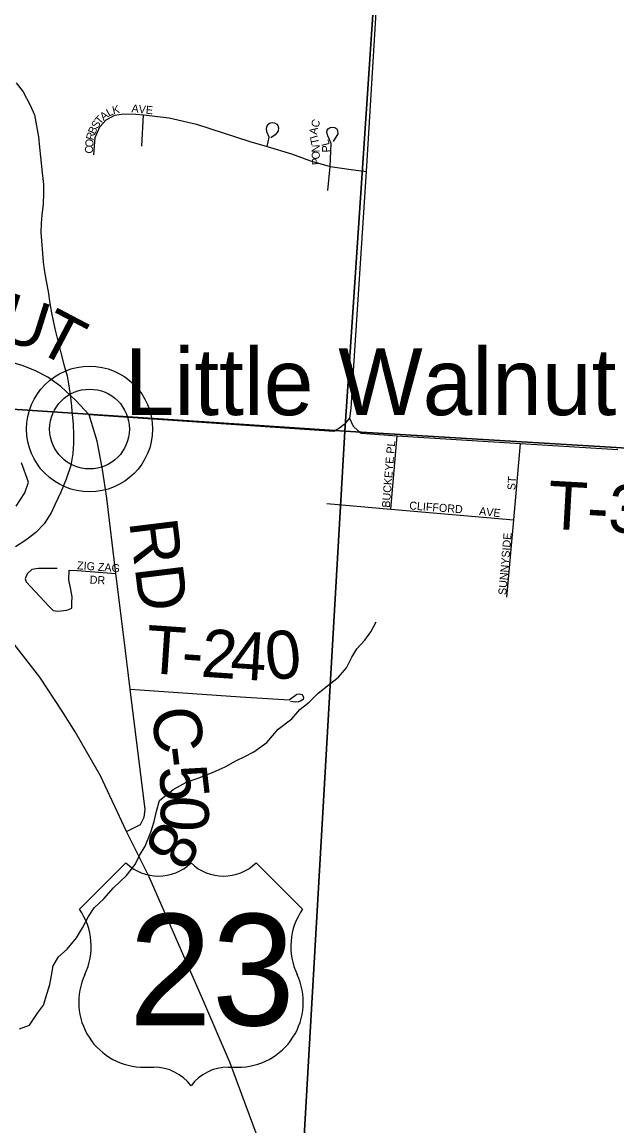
# Model space of a CAD drawing. Extents: x 1643459 to 2064572, y 425441 to 780708.
# Drawn here: x 1835489 to 1839200, y 609399 to 616295 of the extents above; entities that cross this region are included whole.
import ezdxf

# ---------------------------------------------------------------- set-up
doc = ezdxf.new("R2010")
doc.units = 0
for name, color, linetype in [('GE_P_Alignment_100_Curve_Data', 7, 'Continuous'), ('GM_X_Airport_Text_Class_2', 7, 'Continuous'), ('GM_X_County', 7, 'Continuous'), ('GM_X_Major_River', 7, 'Continuous'), ('GM_X_Major_River_Text', 7, 'Continuous'), ('GM_X_Minor_Lake', 7, 'Continuous'), ('GM_X_Rail_Line', 7, 'Continuous'), ('GM_X_Section_Text', 7, 'Continuous'), ('GM_X_State_Route', 7, 'Continuous'), ('GM_X_Township', 7, 'Continuous'), ('GM_X_Township_ROW', 7, 'Continuous'), ('GM_X_Unincorporated_Text', 7, 'Continuous'), ('GM_X_US_Route', 7, 'Continuous'), ('RD_X_Wall', 7, 'Continuous'), ('SH_Named_Boundary', 7, 'Continuous')]:
    doc.layers.add(name, color=color, linetype=linetype)

msp = doc.modelspace()

# ---------------------------------------------------------------- linework, layer by layer
at = {"layer": 'GE_P_Alignment_100_Curve_Data'}
for radius in [392.8, 249]:
    msp.add_circle((1835910, 613753), radius, dxfattribs=at)
at = {"layer": 'GM_X_County'}
for points in [[(1835935.9, 615466.4), (1835945.4, 615575.1), (1835973.8, 615641.3), (1836013.9, 615683.8), (1836068.3, 615714.5), (1836122.6, 615721.6), (1836198.2, 615719.3), (1836246.6, 615716.6), (1836406.2, 615698), (1836576.3, 615657.8), (1836909.5, 615549.1), (1837018.2, 615518.4), (1837169.5, 615471.1), (1837287.6, 615428.5), (1837410.5, 615393.1), (1837528.6, 615375.7), (1837635, 615362.4)], [(1836235.4, 615520.4), (1836246.6, 615716.6)], [(1837018.2, 615518.4), (1837031.1, 615575.8), (1837016.9, 615608.6), (1837013.3, 615632.1), (1837018.3, 615647), (1837027.6, 615659.9), (1837037.5, 615665.5), (1837051.1, 615668.4), (1837064.6, 615666.3), (1837078.1, 615657.7), (1837084.5, 615648.5), (1837089.5, 615633.5), (1837087.4, 615614.3), (1837067.4, 615590.8), (1837041.8, 615572.2)], [(1837410.5, 615393.1), (1837417.8, 615537.1), (1837408.1, 615561.7), (1837396.7, 615585.1), (1837390.4, 615605.1), (1837393.2, 615619.3), (1837399.5, 615627.9), (1837410.9, 615636.5), (1837423.5, 615638.2), (1837440.1, 615636.5), (1837452, 615629.1), (1837457.7, 615618.2), (1837458.9, 615596.5), (1837429.2, 615548.4)], [(1837397.8, 615242.1), (1837410.5, 615393.1)], [(1837789.4, 613252.3), (1837829.5, 613710.6)], [(1838514.2, 612702.1), (1838556.5, 613185.3), (1838598.3, 613663.2)], [(1837390.9, 613287.2), (1837789.4, 613252.3), (1838556.5, 613185.3)], [(1835707.2, 612880.9), (1835591.4, 612882), (1835550.1, 612876.3), (1835521.4, 612848.8), (1835508.8, 612816.7), (1835514.5, 612798.3), (1835655.6, 612645.9), (1835683.1, 612619.5), (1835712.9, 612616), (1835769.1, 612621.8), (1835798.9, 612634.4), (1835798.9, 612669.9), (1835802.3, 612705.5), (1835793.1, 612750.2), (1835781.7, 612809.8), (1835782.8, 612870.6), (1835832.2, 612869.4), (1836073.5, 612851.2)]]:
    msp.add_lwpolyline(points, dxfattribs=at)
at = {"layer": 'GM_X_Major_River_Text'}
for points in [[(1837532.9, 613820.2), (1837555.1, 613770.2), (1837585.7, 613742.4), (1837605.1, 613727.6), (1837829.5, 613710.6), (1838598.3, 613663.2), (1839207.2, 613625.7)], [(1836163.7, 612127.5), (1836850.9, 612080.9), (1837155.6, 612060.5), (1837203.2, 612095.9), (1837217.9, 612099.1), (1837233.9, 612095.3), (1837240.4, 612086.3), (1837244.8, 612075.4), (1837243.5, 612063.9), (1837225.6, 612053), (1837212.8, 612048.5), (1837197.4, 612046.6), (1837164.1, 612051.1)]]:
    msp.add_lwpolyline(points, dxfattribs=at)
at = {"layer": 'GM_X_Minor_Lake'}
for points in [[(1838295.3, 623507.5), (1838285.2, 623456.1), (1838247.4, 623339.1), (1838183.6, 623166.4), (1838147.8, 623052), (1838100, 622903.4), (1838084.3, 622768.9), (1837635, 615362.4), (1837553.3, 614083.1), (1837539.4, 613880.4), (1837532.9, 613820.2), (1837499.6, 613782.2), (1837469.1, 613757.3), (1837433.9, 613736.9), (1835907.7, 613840.6)], [(1836141, 611238.4), (1836227.7, 611282.4), (1836251.6, 611327.7), (1836257.9, 611376.7), (1836163.7, 612127.5), (1836124.9, 612451.9), (1836073.5, 612851.2), (1836018, 613321.9), (1835991, 613500.9), (1835956.6, 613676.2), (1835907.7, 613840.6), (1835825.2, 613931.6), (1835729.8, 614018.5), (1835650.7, 614076.3), (1835572.5, 614117.2), (1835496, 614147.4), (1834666.3, 614394.5), (1834564, 614432.3), (1834468.5, 614470.9), (1834362.4, 614520.7)]]:
    msp.add_lwpolyline(points, dxfattribs=at)
at = {"layer": 'GM_X_Rail_Line'}
msp.add_line((1835910, 613753), (1835910, 613753), dxfattribs=at)
at = {"layer": 'GM_X_State_Route'}
for points in [[(1832445.6, 619408.6), (1837858, 619040.6), (1837502.5, 613740.2), (1832124, 614096)], [(1843212.7, 618736.9), (1842906.5, 613710.2), (1842889.1, 613414.2), (1837502.5, 613740.2), (1837858, 619040.6)], [(1832124, 614096), (1837502.5, 613740.2), (1837194.7, 608395.5), (1831814.4, 608761.4)], [(1842889.1, 613414.2), (1842604.2, 608253.4), (1842595.4, 608085.5), (1837194.7, 608395.5), (1837502.5, 613740.2)]]:
    msp.add_lwpolyline(points, close=True, dxfattribs=at)
at = {"layer": 'GM_X_Unincorporated_Text'}
msp.add_lwpolyline([(1835452.2, 613271.1), (1835506.8, 613355.2), (1835529.2, 613421.3), (1835485.6, 613541.9)], dxfattribs=at)
at = {"layer": 'GM_X_US_Route'}
for points in [[(1835452, 615914.8), (1835495.9, 615858.4), (1835539.7, 615775.9), (1835565.5, 615715.6), (1835579.2, 615647.2), (1835591, 615578.9), (1835598.7, 615510.7), (1835604.5, 615452.4), (1835614.1, 615354), (1835621.8, 615281.7), (1835623.5, 615223.5), (1835621.2, 615157.3), (1835612.9, 615089), (1835608.6, 615038.9), (1835606.4, 614980.7), (1835619.6, 614798), (1835627.4, 614747.8), (1835639.1, 614677.4), (1835650.9, 614611.1), (1835662.6, 614536.8), (1835672.3, 614478.6), (1835694, 614378.1), (1835713.7, 614295.7), (1835731.4, 614229.4), (1835751.1, 614147), (1835770.9, 614084.7), (1835778.7, 614034.5), (1835786.5, 613980.3), (1835796.2, 613916), (1835801.9, 613843.7), (1835807.7, 613783.4), (1835809.4, 613717.2), (1835809.2, 613663), (1835804.9, 613600.8), (1835792.5, 613524.6), (1835764, 613440.4), (1835731.5, 613358.2), (1835693.1, 613280.1), (1835670.8, 613230), (1835626.3, 613159.9), (1835573.9, 613106), (1835511.5, 613058.1), (1835447.1, 613016.2)], [(1836257.4, 611148), (1836291.9, 611234.2), (1836312.2, 611300.3), (1836328.6, 611366.5), (1836346.9, 611432.6), (1836431.5, 611500.5), (1836514, 611546.3), (1836582.3, 611570.1), (1836680.8, 611609.8), (1836755.2, 611643.6), (1836827.6, 611681.4), (1836877.9, 611707.3), (1836934.2, 611737.2), (1837016.7, 611795), (1837087.3, 611877), (1837171.9, 611942.9), (1837222.3, 612000.9), (1837280.7, 612046.8), (1837337.2, 612102.8), (1837405.6, 612156.7), (1837464, 612202.6), (1837512.4, 612260.6), (1837546.9, 612328.7), (1837577.2, 612378.8), (1837627.6, 612434.7), (1837666, 612486.8), (1837698.4, 612548.8)], [(1835473.7, 610005.3), (1835536, 610029.1), (1835584.5, 610103.2), (1835622.8, 610153.2), (1835645.3, 610229.3), (1835661.6, 610283.5), (1835671.8, 610339.6), (1835682.1, 610399.8), (1835716.5, 610455.8), (1835770.9, 610503.8), (1835829.4, 610573.8), (1835865.8, 610637.8), (1835904.2, 610707.9), (1835938.6, 610762), (1835999, 610817.9), (1836059.5, 610885.9), (1836140.2, 610963.8), (1836194.7, 611031.8), (1836221, 611087.9), (1836257.4, 611148)]]:
    msp.add_lwpolyline(points, dxfattribs=at)
at = {"layer": 'RD_X_Wall'}
for points in [[(1836776.3, 609816), (1836628.6, 610159.3), (1836281.8, 610955), (1836141, 611238.4), (1835978.9, 611585.4), (1835819.3, 611861.9), (1835738.9, 611990.7), (1835600.7, 612201.9), (1835439.8, 612408.1), (1835288.3, 612601.2), (1835171.4, 612733.5), (1834849.4, 613077.9)], [(1838632.1, 605573.7), (1838631.4, 605575.4), (1837829.1, 607404.7), (1837579.8, 607966.2), (1837412.6, 608335.9), (1837331.6, 608509.5), (1836955.9, 609337.4), (1836784.4, 609797.3), (1836776.3, 609816)]]:
    msp.add_lwpolyline(points, dxfattribs=at)
at = {"layer": 'SH_Named_Boundary'}
for p, q in [((1836137, 611042.7), (1835846.9, 610752.6)), ((1837239.1, 610752.6), (1836949.1, 611042.7)), ((1836253, 609766.5), (1836311, 609766.5)), ((1836775.1, 609766.5), (1836833.1, 609766.5))]:
    msp.add_line(p, q, dxfattribs=at)
for centre, radius, start, end in [((1836340, 611249.8), 290, 225.573, 314.427), ((1836746.1, 611249.8), 290, 225.573, 314.427), ((1835514.3, 610519.7), 406.1, 334.54712, 35.00093), ((1837571.8, 610519.7), 406.1, 144.99907, 205.45288), ((1836248.5, 610172.5), 406.1, 154.83192, 270.63826), ((1836837.6, 610172.5), 406.1, 269.36174, 25.16808), ((1836311, 609476.4), 290, 36.8699, 90), ((1836775.1, 609476.4), 290, 90, 143.1301)]:
    msp.add_arc(centre, radius, start, end, dxfattribs=at)

# ---------------------------------------------------------------- texts
at = {"layer": 'GM_X_Airport_Text_Class_2'}
for s in ['/', '0']:
    msp.add_text(s, height=1, dxfattribs=at).set_placement((1836542.7, 610370.1))
msp.add_text('23', height=1, rotation=0.00001, dxfattribs=at).set_placement((1836336.2, 610163.1))
at = {"layer": 'GM_X_Major_River'}
for s, rotation, p in [('T-31', 356.81995, (1838763, 613131.1)), ('T', 356.12165, (1836254.7, 612229.9)), ('2', 356.12492, (1836600, 612206.5)), ('4', 356.14355, (1836783, 612194.1)), ('0', 5.8033, (1837021, 612182.7)), ('-', 356.12179, (1836478.2, 612214.7))]:
    msp.add_text(s, height=300, rotation=rotation, dxfattribs=at).set_placement(p)
at = {"layer": 'GM_X_Section_Text'}
for s, rotation, p in [('U', 342.55232, (1835323.4, 614322.3)), ('T', 332.28298, (1835562.1, 614248.6)), ('RD', 277.00583, (1836156.5, 613175.3)), ('C', 277.0486, (1836294.4, 612000.6)), ('-', 277.02694, (1836324.4, 611758)), ('5', 276.5529, (1836339.3, 611637.4)), ('0', 267.28497, (1836359.8, 611468.1)), ('8', 237.54282, (1836363.4, 611323.8))]:
    msp.add_text(s, height=300, rotation=rotation, dxfattribs=at).set_placement(p)
at = {"layer": 'GM_X_Township'}
for s, rotation, p in [('A', 37.8098, (1835997.5, 615677.3)), ('L', 28.44693, (1836030.5, 615703)), ('K', 13.99384, (1836058.3, 615718.6)), ('AVE', 354.0985, (1836170.2, 615732.5)), ('S', 58.0757, (1835958.7, 615624.4)), ('T', 48.53657, (1835976, 615652.6)), ('C', 67.63042, (1837334, 615630.6)), ('R', 75.61619, (1835934.5, 615553.6)), ('B', 66.17313, (1835943.6, 615589.9)), ('A', 83.09731, (1837329.6, 615590.4)), ('C', 87.23095, (1835930.8, 615472.7)), ('O', 87.23421, (1835932.8, 615512.3)), ('I', 106.70199, (1837335.5, 615574.7)), ('T', 101.97374, (1837343.9, 615535.9)), ('N', 91.22134, (1837346, 615481.8)), ('L', 104.34365, (1837408.5, 615529)), ('P', 90.9289, (1837410.7, 615481.4)), ('O', 91.20951, (1837346.9, 615437.8)), ('P', 91.20203, (1837347.6, 615402.6)), ('BUCKEYE PL', 85.29211, (1837783.2, 613260)), ('ST', 86.42621, (1838566.4, 613369.8)), ('CLIFFORD', 355.73128, (1837903.3, 613250.9)), ('AVE', 354.09695, (1838339.2, 613215.7)), ('SUNNYSIDE', 84.9363, (1838509.3, 612714.4)), ('ZIG ZAG', 355.83871, (1835830.9, 612877)), ('DR', 356.98902, (1835909.9, 612787.6))]:
    msp.add_text(s, height=50, rotation=rotation, dxfattribs=at).set_placement(p)
at = {"layer": 'GM_X_Township_ROW'}
msp.add_text('Little Walnut', height=417, rotation=0.00001, dxfattribs=at).set_placement((1836129.4, 613839.7))
at = {"layer": 'SH_Named_Boundary'}
msp.add_text('23', height=696.1, dxfattribs=at).set_placement((1836155.6, 610027.5))

doc.saveas('drawing.dxf')
